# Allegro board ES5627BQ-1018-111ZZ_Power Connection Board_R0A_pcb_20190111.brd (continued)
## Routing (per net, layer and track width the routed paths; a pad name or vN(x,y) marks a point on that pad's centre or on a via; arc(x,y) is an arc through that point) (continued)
VCC12: length 191.4
  TOP w0.381: 49.62,29.94 50.1,30.42 C36.1
  TOP w0.635: CONN5.1 44.59,33.14 ; CONN5.1 43.88,31.49 ; CONN5.1 44.59,31.71 ; CONN5.1 44.82,32.43
  TOP w0.762: CONN20.3 53.95,45.38 ; CONN20.3 51.62,44.39 ; CONN20.3 52.61,46.71 ; CONN20.3 53.61,44.39 ; CONN20.3 51.28,45.38 ; CONN20.3 53.61,46.37 ; CONN20.3 51.62,46.37 ; CONN20.3 52.61,44.05 ; CONN20.16 49.41,49.89 ; CONN20.16 47.42,51.87 ; CONN20.16 49.75,50.88 ; CONN20.16 48.41,49.55 ; CONN20.16 48.41,52.21 ; CONN20.16 47.42,49.89 ; CONN20.16 49.41,51.87 ; CONN20.16 47.08,50.88 ; CONN20.15 52.61,52.21 ; CONN20.15 53.61,51.87 ; CONN20.15 51.62,49.89 ; CONN20.15 51.28,50.88 ; CONN20.15 53.95,50.88 ; CONN20.15 51.62,51.87 ; CONN20.15 52.61,49.55 ; CONN20.15 53.61,49.89 ; CONN20.4 49.75,45.38 ; CONN20.4 49.41,44.39 ; CONN20.4 47.42,44.39 ; CONN20.4 47.42,46.37 ; CONN20.4 48.41,44.05 ; CONN20.4 47.08,45.38 ; CONN20.4 48.41,46.71 ; CONN20.4 49.41,46.37
  V5 w0.635: CONN5.1 44.59,31.71 ; CONN5.1 44.59,33.14 ; CONN5.1 44.82,32.43 ; CONN5.1 43.88,31.49
  V5 w0.762: 51.28,50.88 CONN20.15 ; CONN20.15 53.61,49.89 ; CONN20.15 53.95,50.88 ; CONN20.15 52.61,49.55 ; CONN20.15 52.61,52.21 ; CONN20.15 51.62,51.87 ; CONN20.15 51.62,49.89 ; CONN20.15 53.61,51.87 ; 51.62,46.37 CONN20.3 ; CONN20.3 51.62,44.39 ; CONN20.3 53.61,44.39 ; CONN20.3 52.61,44.05 ; CONN20.3 51.28,45.38 ; CONN20.3 52.61,46.71 ; CONN20.3 53.95,45.38 ; CONN20.3 53.61,46.37 ; CONN20.4 48.41,46.71 ; CONN20.4 49.41,44.39 ; CONN20.4 49.41,46.37 ; CONN20.4 48.41,44.05 ; CONN20.4 49.75,45.38 ; CONN20.4 47.42,46.37 ; CONN20.4 47.42,44.39 ; CONN20.4 47.08,45.38 ; CONN20.16 49.41,49.89 ; CONN20.16 48.41,52.21 ; CONN20.16 47.42,51.87 ; CONN20.16 47.08,50.88 ; CONN20.16 48.41,49.55 ; CONN20.16 47.42,49.89 ; CONN20.16 49.75,50.88 ; CONN20.16 49.41,51.87
  V6 w0.635: 43.88,31.49 CONN5.1 ; CONN5.1 44.82,32.43 ; CONN5.1 44.59,33.14 ; CONN5.1 44.59,31.71
  V6 w0.762: CONN20.16 49.41,49.89 ; CONN20.16 48.41,52.21 ; CONN20.16 47.42,51.87 ; CONN20.16 47.42,49.89 ; CONN20.16 48.41,49.55 ; CONN20.16 49.75,50.88 ; CONN20.16 49.41,51.87 ; CONN20.16 47.08,50.88 ; 48.41,44.05 CONN20.4 ; CONN20.4 47.42,46.37 ; CONN20.4 49.41,46.37 ; CONN20.4 49.41,44.39 ; CONN20.4 47.08,45.38 ; CONN20.4 48.41,46.71 ; CONN20.4 49.75,45.38 ; CONN20.4 47.42,44.39 ; CONN20.15 53.61,51.87 ; CONN20.15 51.28,50.88 ; CONN20.15 52.61,49.55 ; CONN20.15 51.62,49.89 ; CONN20.15 52.61,52.21 ; CONN20.15 53.61,49.89 ; CONN20.15 51.62,51.87 ; CONN20.15 53.95,50.88 ; 51.62,46.37 CONN20.3 ; CONN20.3 52.61,44.05 ; CONN20.3 53.61,44.39 ; CONN20.3 52.61,46.71 ; CONN20.3 51.62,44.39 ; CONN20.3 53.61,46.37 ; CONN20.3 53.95,45.38 ; CONN20.3 51.28,45.38
  BOTTOM w0.381: C127.1 46.62,38.8 ; C118.2 53.46,38.6 53.43,38.63 ; C115.1 46.67,37.79 46.7,37.76 ; C122.2 53.33,39.64 53.25,39.57
  BOTTOM w0.635: CONN5.1 43.88,33.37 ; CONN5.1 44.59,31.71 ; CONN5.1 44.59,33.14 ; CONN5.1 44.82,32.43
  BOTTOM w0.762: CONN20.16 49.75,50.88 ; CONN20.16 47.42,51.87 ; CONN20.16 48.41,52.21 ; CONN20.16 49.41,49.89 ; CONN20.16 48.41,49.55 ; CONN20.16 49.41,51.87 ; CONN20.16 47.42,49.89 ; CONN20.16 47.08,50.88 ; 51.28,50.88 CONN20.15 ; CONN20.15 51.62,51.87 ; CONN20.15 52.61,49.55 ; CONN20.15 52.61,52.21 ; CONN20.15 51.62,49.89 ; CONN20.15 53.61,49.89 ; 47.42,46.37 CONN20.4 ; CONN20.4 48.41,44.05 ; CONN20.4 49.41,44.39 ; CONN20.4 47.08,45.38 ; CONN20.4 49.41,46.37 ; CONN20.4 47.42,44.39 ; CONN20.4 48.41,46.71 ; CONN20.4 49.75,45.38 ; CONN20.3 52.61,46.71 ; CONN20.3 51.62,44.39 ; CONN20.3 52.61,44.05 ; CONN20.3 53.61,44.39 ; CONN20.3 53.61,46.37 ; CONN20.3 51.62,46.37 ; CONN20.3 51.28,45.38
  vias: v1(48.98,37.79) v1(50.66,35.4) v1(51.19,33.34) v1(51.9,38.75) v1(52.39,36.7) v2(45.55,32.76) v2(45.58,31.79) v2(45.6,30.85) v2(46.16,35.2) v2(46.77,32.73) v2(46.8,31.77) v2(46.82,30.83) v2(47.25,35.22) v2(47.76,39.31) v2(47.76,32.73) v2(47.79,31.77) v2(47.81,30.83) v2(48.02,40.58) v2(48.32,35.22) v2(48.55,41.9) v2(48.75,32.76) v2(48.78,31.79) v2(48.8,30.85) v2(49.26,40.51) v2(49.34,39.16) v2(49.39,35.25) v2(49.67,41.93) v2(50.61,41.93) v2(51.01,40.48) v2(51.72,41.83) v2(52.54,41.75)
BS_USB_VCC5P0: length 3.3
  TOP w0.381: v2(81.06,37.18) 81.06,37.23 81,37.29 U2.1
  BOTTOM w0.127: C24.1 82.2,38.42 v1(82.28,38.35)
  BOTTOM w0.381: C24.1 80.99,37.3 81.06,37.23 v2(81.06,37.18)
BS_VSTB_3V3: length 3.6
  TOP w0.381: U1.12 v2(88.81,34.36)
  BOTTOM w0.127: v2(88.81,34.36) 89.29,34.84 v1(89.77,34.84)
  BOTTOM w0.381: C29.1 87.59,34.36 v2(88.81,34.36)
CPLD_VDD1P8: length 37.5
  TOP w0.381: 12.91,39.24 12.89,39.26 C83.1 13.35,39.8 14.1,40.55 R64.1 ; 11.87,39.26 11.88,39.27 C85.1 ; C86.1 10.88,39.21
  TOP w0.635: 6.18,38.48 CONN11.1 ; CONN11.1 7.84,37.76 ; CONN11.1 7.61,38.48 ; CONN11.1 6.9,36.82 ; CONN11.1 7.61,37.05 ; CONN11.1 6.9,38.7
  TOP w0.762: CONN20.22 23.21,52.21 ; CONN20.22 22.22,51.87 ; CONN20.22 21.88,50.88 ; CONN20.22 24.21,51.87 ; CONN20.22 24.55,50.88 ; CONN20.22 24.21,49.89 ; CONN20.22 22.22,49.89 ; CONN20.22 23.21,49.55
  BOTTOM w0.381: C105.1 16.24,40.22 16.24,40.23
  BOTTOM w0.635: CONN11.1 7.84,37.76 ; CONN11.1 7.61,37.05 ; CONN11.1 6.9,38.7 ; CONN11.1 7.61,38.48 ; CONN11.1 6.9,36.82
  BOTTOM w0.762: CONN20.22 24.21,49.89 ; CONN20.22 21.88,50.88 ; CONN20.22 23.21,52.21 ; CONN20.22 24.55,50.88 ; CONN20.22 22.22,49.89 ; CONN20.22 23.21,49.55 ; CONN20.22 22.22,51.87 ; CONN20.22 24.21,51.87
  vias: v1(9.02,39.65) v1(9.42,42.16) v1(11.58,43.36) v1(13.09,39.67) v1(15.33,39.59) v2(9.15,36.92) v2(9.41,37.76) v2(9.64,38.63) v2(9.99,36.92) v2(10.3,37.76) v2(10.42,38.63) v2(10.86,36.95) v2(11.21,37.69) v2(11.34,38.63)
CPLD_VDD1P8_FB: length 4.8
  TOP w0.127: U4.16 v2(15.21,37.54)
  TOP w0.305: U4.16 14.52,39.61 R64.2
  TOP w0.356: R64.2 R63.2
  BOTTOM w0.127: v1(16.16,37.58) 16.12,37.54 v2(15.21,37.54)
CPLD_VDD1P8_PG: length 103.5
  TOP w0.127: CONN19.4 v2(99.96,34.41)
  TOP w0.254: U4.9 v2(13.87,31.45)
  S3 w0.127: v2(13.87,31.45) 14.2,31.78 19.69,31.78 20.32,31.15 24.89,31.15 26.29,32.54 32.33,32.54 33.12,31.75 34.24,31.75 36.36,33.87 36.36,33.88 36.63,34.15 36.64,34.15 38.36,35.87 45.22,35.87 45.5,36.15 84.3,36.15 84.61,36.45 92.81,36.45 94.65,34.61 99.76,34.61 v2(99.96,34.41)
  BOTTOM w0.127: v2(13.87,31.45) v1(12.06,31.45) 11.26,31.45 10.63,32.08 6.79,32.08 CONN13.1
  BOTTOM w0.254: v2(13.87,31.45) 13.87,30.23 R67.2
CPLD_VDD1P8_SS: length 3.4
  TOP w0.254: C87.1 17.52,36.34 v2(17.23,36.34) U4.15
  BOTTOM w0.127: v1(18.15,36.21) 18.01,36.34 v2(17.23,36.34)
CPLD_VDD1P8_VIN: length 2.8
  TOP w0.381: C93.1 9.79,30.8 ; C90.1 10.81,30.8 ; C92.1 11.82,30.78
  BOTTOM w0.127: v2(8.6,31.06) v1(9.53,31.06)
EN_CPLD_VDD1P8_R: length 6.7
  TOP w0.254: U4.11 16.47,33.74 v2(17.02,33.2) 17.51,32.71 C89.1 RB22.2 R66.2 R65.1
  BOTTOM w0.127: v1(17.82,32.86) 17.47,33.2 v2(17.02,33.2)
EN_MANG_1P2_R: length 6.4
  TOP w0.254: RB24.1 30.04,34.61 C94.1 R68.2 ; U5.11 v2(28.84,33.57) 30.02,33.57 R68.2 ; R68.2 30.09,32.5 RB23.2
  BOTTOM w0.127: v2(28.84,33.57) 28.99,33.41 v1(28.99,32.71)
EN_USB_VCC5P0_R: length 7.3
  TOP w0.127: R15.1 v2(69.63,39.21)
  TOP w0.254: R15.1 R14.1 71.38,39.18 CB4.2 RB3.2 73.52,39.11 U2.7
  BOTTOM w0.127: v1(69,39.97) 69,39.84 v2(69.63,39.21)
FB_USB_VCC5P0: length 5.9
  TOP w0.254: U2.5 v2(74.46,41.65) 73.49,41.65 C43.2 73.37,41.57 R16.1 72.04,41.57 R13.2
  BOTTOM w0.127: v1(73.57,41.5) 73.72,41.65 v2(74.46,41.65)
FB_VSTB_3V3: length 6
  TOP w0.254: U1.2 v2(80.75,35.01) 79.4,35.01 C9.2 R2.1
  BOTTOM w0.127: v1(82.08,35.86) 81.8,35.58 R1.1
  BOTTOM w0.254: R1.1 81.58,35.01 v2(80.75,35.01)
FPGA_1V2: length 52.5
  TOP w0.254: R62.2 12.58,27.73 12.71,27.6 v2(14.67,27.6)
  TOP w0.635: 28.28,21.28 CONN10.1 ; CONN10.1 29.22,20.34 ; CONN10.1 29.94,20.56 ; CONN10.1 28.51,20.56 ; CONN10.1 30.16,21.28
  V5 w0.635: 28.51,21.99 CONN10.1 ; CONN10.1 28.51,20.56 ; CONN10.1 29.22,22.22 ; CONN10.1 28.28,21.28 ; CONN10.1 29.94,20.56 ; CONN10.1 30.16,21.28 ; CONN10.1 29.22,20.34 ; CONN10.1 29.94,21.99
  V5 w0.762: 26.08,45.38 CONN20.9 ; CONN20.9 26.42,46.37 ; CONN20.9 28.41,46.37 ; CONN20.9 27.41,44.05 ; CONN20.9 28.41,44.39 ; CONN20.9 26.42,44.39 ; CONN20.9 27.41,46.71 ; CONN20.9 28.75,45.38
  BOTTOM w0.254: v2(14.67,27.6) 20.18,27.6 24.14,23.64 24.14,21.48 24.47,21.15 C80.1
  BOTTOM w0.381: C110.2 27.41,40.78 CONN20.9 ; C79.1 26.63,20.21 v2(26.66,20.19) ; C80.1 v2(25.16,20.16)
  BOTTOM w0.635: 28.28,21.28 CONN10.1 ; CONN10.1 29.22,20.34 ; CONN10.1 28.51,20.56 ; CONN10.1 30.16,21.28 ; CONN10.1 29.94,20.56
  vias: v1(25.39,19.12) v2(26.81,19.42) v2(27.65,20.97) v2(27.65,20.08)
FPGA_1V2_BST: length 3.3
  TOP w0.127: U3.12 20.18,24.83 20.25,24.76 v2(20.41,24.76)
  BOTTOM w0.127: v1(21.3,25.16) 20.89,24.76 v2(20.41,24.76) 20.33,24.68 19.72,24.68 CB10.1
FPGA_1V2_EN_R: length 9
  TOP w0.127: v2(11.67,18.76) 11.18,19.25 R57.1 ; R57.1 12.23,20.79 R56.1 ; R57.1 11.18,21.31 11.17,21.32 R58.2 11.17,22.26 11.18,22.27 C63.1 11.64,22.78 12.19,22.23 U3.7
  BOTTOM w0.127: v2(11.67,18.76) 12.13,19.22 v1(12.56,19.22)
FPGA_1V2_FB: length 6.1
  TOP w0.127: U3.2 12.16,25.48 11.99,25.65 C65.2 R61.1 v2(10.4,24.88)
  BOTTOM w0.127: v1(9.74,24.1) 10.4,24.76 v2(10.4,24.88) 11.08,24.88 R60.2
FPGA_1V2_PG: length 10.9
  TOP w0.127: U3.6 12.62,22.88 12.61,22.89 12.11,22.89 11.34,23.67 11.34,23.74 R59.1 11.23,23.85 8.49,23.85 7.92,24.41 7.92,25.34 7.87,25.39 CONN9.1
  BOTTOM w0.127: CONN9.1 7.87,27.29 8.19,27.61 8.19,28.54 v1(8.43,28.78)
FPGA_1V2_SS: length 3.3
  TOP w0.127: U3.4 12.58,24.18 12.51,24.25 v2(12.35,24.25)
  BOTTOM w0.127: v1(14.34,24.35) 14.31,24.37 C64.1 13.32,24.35 12.46,24.35 v2(12.35,24.25)
FPGA_1V2_SW: length 2.9
  BOTTOM w0.127: v1(20.79,22.75) 20.41,23.13 v2(20.41,23.54)
  BOTTOM w0.254: RB25.1 19.54,22.6 CB10.2 20.35,23.59 v2(20.41,23.54)
FPGA_1V2_VIN: length 12.6
  TOP w0.254: R56.2 13.69,20.77 13.75,20.83 15.31,20.83 15.35,20.87 16.42,20.87 v2(16.8,20.49)
  TOP w0.381: 21.02,25.93 21.04,25.95 C74.1
  BOTTOM w0.254: v2(20.38,25.9) 19.03,25.9 v1(18.98,25.85) 18.22,25.09 18.22,21.56 17.16,20.49 v2(16.8,20.49)
FPGA_1V2_VO: length 6.7
  TOP w0.127: v2(14.77,26.13) U3.1 12,26.13 11.61,26.52 11.46,26.52 C65.1 R61.2 R62.1
  BOTTOM w0.127: v2(14.77,26.13) 15.43,26.79 v1(15.5,26.79)
FPGA_1V2_VREG5: length 5.1
  TOP w0.127: U3.3 12.59,24.83 12.43,24.99 v2(12.4,24.99) 12.1,24.68 R59.2
  BOTTOM w0.127: v1(12.08,26.18) 12.08,25.31 v2(12.4,24.99) 13.11,25.7 CB9.2
FPGA_2V5: length 21.5
  TOP w0.381: 32.17,39.16 32.14,39.18 C123.1 ; C119.1 33.18,39.18 33.16,39.16 ; 31.07,39.18 31.1,39.21 C88.1
  TOP w0.762: CONN20.21 28.41,49.89 ; CONN20.21 28.41,51.87 ; CONN20.21 26.42,51.87 ; CONN20.21 28.75,50.88 ; CONN20.21 26.42,49.89 ; CONN20.21 26.08,50.88 ; CONN20.21 27.41,52.21 ; CONN20.21 27.41,49.55
  BOTTOM w0.381: 31.71,35.58 31.81,35.48 R75.2 ; C124.2 31.63,36.49 31.61,36.52
  BOTTOM w0.635: 32.85,32.86 CONN16.1 ; CONN16.1 33.08,32.14 ; CONN16.1 33.79,33.8 ; CONN16.1 34.51,32.14 ; CONN16.1 33.79,31.92 ; CONN16.1 33.08,33.58 ; CONN16.1 34.51,33.58 ; CONN16.1 34.74,32.86
  vias: v1(31.38,33.77) v2(30.9,38.6) v2(30.92,37.71) v2(31.81,38.63) v2(31.76,37.74) v2(32.73,37.79) v2(32.78,38.6)
FPGA_2V5_EN: length 7
  TOP w0.127: R74.1 43.24,35.32 v2(43.74,34.83)
  TOP w0.356: C113.1 39.95,35.45 39.68,35.72 U6.5
  TOP w0.381: R74.1 R72.1 R73.2 C113.1
  BOTTOM w0.127: v1(44.59,35.17) 44.24,34.83 v2(43.74,34.83)
FPGA_2V5_FB: length 4.7
  TOP w0.356: U6.3 v2(33.94,36.37) 33.23,36.37 R76.2
  BOTTOM w0.127: v1(34.51,35.81) v2(33.94,36.37)
  BOTTOM w0.356: R75.1 C124.1 33.23,36.37 v2(33.94,36.37)
FPGA_2V5_IN: length 2.7
  TOP w0.381: L9.2 42.23,37.51 R72.2
  BOTTOM w0.127: v2(39.41,38.02) v1(40.4,38.02)
HEATER_VCC12: length 89.8
  TOP w0.381: C33.1 95.87,37.99 96.09,38.2 96.09,38.63 96.23,38.78 v2(96.23,38.82) ; C33.1 95.46,38.24 v2(95.46,38.75) ; C33.1 94.6,37.99 L2.1 ; 66.15,30.57 66.23,30.5 C66.1 ; v2(27.98,26.38) 27.75,26.38 27.26,26.87 L5.2 27.57,27.4 v2(28.2,27.4) ; C98.2 62.98,45.35 62.98,45.36 ; v2(87.77,42) LB1.1 v2(88.73,40.86)
  TOP w0.635: CONN8.1 59.86,31.46 ; CONN8.1 58.92,32.4 ; CONN8.1 59.63,32.18 ; CONN8.1 57.98,31.46 ; CONN8.1 59.63,30.75 ; CONN8.1 58.2,32.18
  TOP w0.762: 61.01,44.05 CONN20.1 ; CONN20.1 62.35,44.05 ; CONN20.1 59.68,45.38 ; CONN20.1 61.01,46.71 ; CONN20.1 62.35,45.38 ; CONN20.1 59.68,46.71 ; CONN20.1 62.35,46.71 ; CONN20.1 59.68,44.05
  S3 w0.635: CONN8.1 58.92,32.4 ; CONN8.1 58.92,30.52 ; CONN8.1 59.63,32.18 ; CONN8.1 59.63,30.75 ; CONN8.1 59.86,31.46 ; CONN8.1 58.2,30.75 ; CONN8.1 58.2,32.18 ; CONN8.1 57.98,31.46
  V5 w0.635: 57.98,31.46 CONN8.1 ; CONN8.1 59.63,32.18 ; CONN8.1 58.92,32.4 ; CONN8.1 59.63,30.75 ; CONN8.1 59.86,31.46 ; CONN8.1 58.2,32.18
  V5 w0.762: CONN20.1 62.35,45.38 ; CONN20.1 60.02,46.37 ; CONN20.1 61.01,44.05 ; CONN20.1 62.01,46.37 ; CONN20.1 59.68,45.38 ; CONN20.1 61.01,46.71 ; CONN20.1 62.01,44.39 ; CONN20.1 60.02,44.39
  V6 w0.635: CONN8.1 59.63,32.18 ; CONN8.1 58.2,32.18 ; CONN8.1 57.98,31.46 ; CONN8.1 58.2,30.75 ; CONN8.1 58.92,30.52 ; CONN8.1 58.92,32.4 ; CONN8.1 59.86,31.46 ; CONN8.1 59.63,30.75
  V6 w0.762: 60.02,46.37 CONN20.1 ; CONN20.1 59.68,45.38 ; CONN20.1 62.01,46.37 ; CONN20.1 60.02,44.39 ; CONN20.1 61.01,44.05 ; CONN20.1 62.01,44.39 ; CONN20.1 62.35,45.38 ; CONN20.1 61.01,46.71
  BOTTOM w0.635: CONN8.1 59.63,30.75 ; CONN8.1 58.2,32.18 ; CONN8.1 59.63,32.18 ; CONN8.1 59.86,31.46 ; CONN8.1 58.92,32.4 ; CONN8.1 57.98,31.46
  BOTTOM w0.762: 59.68,45.38 CONN20.1 ; CONN20.1 61.01,46.71 ; CONN20.1 62.01,46.37 ; CONN20.1 61.01,44.05 ; CONN20.1 62.35,45.38 ; CONN20.1 62.01,44.39 ; CONN20.1 60.02,46.37 ; CONN20.1 60.02,44.39
  vias: v1(59.55,37.76) v1(60.77,36.09) v1(62.22,33.8) v1(62.67,37.43) v1(64.6,33.75) v2(29.12,26.54) v2(29.2,27.4) v2(58.99,40) v2(58.96,38.93) v2(59.07,35.07) v2(59.85,38.93) v2(60.13,39.95) v2(60.21,35.04) v2(60.72,31.34) v2(60.84,38.93) v2(60.77,32.56) v2(61.12,40) v2(61.35,35.1) v2(62.09,38.93) v2(62.09,32.56) v2(62.06,31.41) v2(62.34,40.02) v2(62.44,35.1) v2(63.28,32.56) v2(63.31,31.41) v2(63.99,35.15) v2(64.45,32.5) v2(64.53,31.36) v2(88.7,42.19) v2(89.53,42.21) v2(89.48,41.38)
HGATE_MB1: length 5.3
  TOP w0.254: v2(44.84,30.17) 44.84,29.2 Q11.4
  BOTTOM w0.254: R81.2 41.74,30.83 v1(42.38,30.19) 42.4,30.17 v2(44.84,30.17)
HGATE_MB2: length 7.5
  TOP w0.254: Q12.4 v2(62.57,29.33)
  BOTTOM w0.254: R86.2 66.92,29.33 v1(66.38,29.33) v2(62.57,29.33)
I2C_SCL_PS1: length 12.8
  BOTTOM w0.127: v1(38.52,20.39) 38.1,19.98 Q8.C2 38.06,18.97 R45.1 38.06,14.09 R91.1 38.08,13.6 35.82,11.34 CONNB1.19
I2C_SCL_PS2: length 15.9
  TOP w0.127: Q5.C1 92.36,18.38 v2(92.36,17.39) 92.36,15.55 91.91,15.09 R35.1 R93.1 91.91,12.71 92.54,12.08 96.48,12.08 98.07,10.49 CONNB2.19
  BOTTOM w0.127: v2(92.36,17.39) v1(92.36,18.29)
I2C_SDA_PS1: length 15.1
  BOTTOM w0.127: v1(40.52,20.21) 40.39,20.08 Q3.C1 40.39,18.14 40.09,17.84 40.09,15.93 40.37,15.65 R46.1 R92.1 40.37,13.63 40.07,13.33 38.8,13.33 37.09,11.62 CONNB1.20
I2C_SDA_PS2: length 18.3
  TOP w0.127: CONNB2.20 98.12,7.47 97.14,8.45 97.14,9.9 95.39,11.65 92.24,11.65 90.61,13.28 R94.1 R36.1 90.57,14.66 v2(90.57,17.29) Q5.C2
  BOTTOM w0.127: v1(91.15,16.58) 90.57,17.16 v2(90.57,17.29)
LGND_USB_VCC5P0: length 2.6
  TOP w0.254: v2(70.37,39.98) 70.37,40.76 R13.1
  BOTTOM w0.254: C42.2 74.38,39.13 R12.2
  vias: v1(71.73,40.98)
LGND_VSTB_3V3: length 7.5
  TOP w0.254: v2(80.63,32.78) 80.78,32.78 81.06,33.06 U1.5
  BOTTOM w0.127: v1(78.56,30.94) R6.2
  BOTTOM w0.508: R1.2 80.7,32.78 v2(80.63,32.78) 80.35,32.5 C5.2 79.31,31.51 R6.2
MANG_1P2: length 36.9
  TOP w0.356: 25.23,38.93 25.26,38.96 C100.1 25.31,39.57 R70.1 ; C102.1 23.23,38.96 23.28,38.91 ; C104.1 24.24,38.96
  TOP w0.635: CONN15.1 20.71,38.7 ; CONN15.1 20,40.35 ; CONN15.1 20,38.47 ; CONN15.1 20.94,39.41 ; CONN15.1 19.28,40.13 ; CONN15.1 20.71,40.13
  TOP w0.762: 22.22,44.39 CONN20.10 ; CONN20.10 24.21,44.39 ; CONN20.10 21.88,45.38 ; CONN20.10 24.55,45.38 ; CONN20.10 22.22,46.37 ; CONN20.10 23.21,46.71 ; CONN20.10 24.21,46.37 ; CONN20.10 23.21,44.05
  BOTTOM w0.356: C106.2 v2(22.13,40.48)
  BOTTOM w0.635: CONN15.1 20.71,38.7 ; CONN15.1 20,38.47 ; CONN15.1 20,40.35 ; CONN15.1 20.71,40.13 ; CONN15.1 20.94,39.41
  BOTTOM w0.762: CONN20.10 24.55,45.38 ; CONN20.10 23.21,46.71 ; CONN20.10 24.21,44.39 ; CONN20.10 22.22,46.37 ; CONN20.10 21.88,45.38 ; CONN20.10 24.21,46.37 ; CONN20.10 23.21,44.05 ; CONN20.10 22.22,44.39
  vias: v1(23.86,41.75) v2(21.17,40.45) v2(21.19,38.04) v2(21.6,37.48) v2(21.65,39.01) v2(22.21,39.62) v2(22.26,38.47) v2(22.59,37.43) v2(23.33,38.04)
MANG_1P2_FB: length 4.4
  TOP w0.305: U5.16 26.63,38.25 v2(26.71,38.32)
  TOP w0.356: R69.2 27.24,39.59 R70.2 27.21,38.83 v2(26.71,38.32)
  BOTTOM w0.127: v2(26.71,38.32) 26.6,38.42 v1(25.87,38.42)
MANG_1P2_PG: length 94.5
  TOP w0.127: v2(103.41,35.18) 103.73,35.18 104.23,35.68 CONN19.5
  TOP w0.254: U5.9 v2(25.98,31.33)
  S3 w0.127: v2(103.41,35.18) 103.79,34.81 103.79,33.99 101.32,31.51 73.47,31.51 70.63,34.36 43.54,34.36 43.17,34.73 40.35,34.73 36.26,30.64 31.93,30.64 31.21,31.35 29.94,31.35 29.91,31.33 v2(25.98,31.33)
  BOTTOM w0.127: CONN14.1 30.46,30.65 29.79,31.33 v1(27.21,31.33) v2(25.98,31.33)
  BOTTOM w0.254: R71.2 25.98,30.23 v2(25.98,31.33)
MANG_1P2_SS: length 2.9
  TOP w0.254: U5.15 v2(28.79,36.17)
  BOTTOM w0.127: v1(28,35.35) 27.9,35.45 C96.1
  BOTTOM w0.254: v2(28.79,36.17) 28.66,36.29 C96.1
MANG_1P2_VIN: length 2
  BOTTOM w0.356: 23.1,30.83 23.02,30.75 C101.1 ; C99.1 24.04,30.73 24.09,30.78
  BOTTOM w0.381: C103.1 20.71,31.69 20.79,31.77
  vias: v1(21.22,32.5) v2(22.18,32.45) v2(22.18,31.67) v2(23.15,32.45) v2(23.15,31.62)
MB1_PWR_EN: length 77.9
  TOP w0.127: CONN19.7 v2(103.85,36.95)
  S3 w0.127: v2(103.85,36.95) 103.32,36.43 103.32,35.97 103.61,35.68 104.07,35.68 104.18,35.58 104.18,33.5 102.7,32.03 v2(102.7,31.95) 101.84,31.08 73.37,31.08 70.51,33.93 41.83,33.93 38.31,30.42 v2(38.31,30.17)
  BOTTOM w0.127: v2(102.7,31.95) 103.29,31.36 v1(103.57,31.36) ; R79.2 37.75,30.73 v2(38.31,30.17)
PS1_12V_PG: length 5.7
  TOP w0.127: CONN19.11 105.56,39.36 v2(103.95,39.36)
  BOTTOM w0.127: v1(103.14,38.75) 103.74,39.36 v2(103.95,39.36) R40.1 105.68,39.36 R21.1 105.7,38.32 R20.2
PS1_12V_PG_R: length 94.3
  S3 w0.127: v2(31.68,17.95) 32.52,18.8 61,18.8 61.98,19.78 77.48,19.78 78.7,21 94.43,21 104.96,31.53 104.96,37.46 v2(103.9,38.52)
  BOTTOM w0.127: R41.1 33.37,15.1 33.35,15.08 R55.2 32.27,15.08 31.68,15.67 v2(31.68,17.95) Q7.C1 31.68,20.07 v1(31.48,20.26) ; R40.2 103.97,38.45 v2(103.9,38.52)
PS1_A0: length 16.2
  BOTTOM w0.127: CONNB1.3 40.9,4.93 41.98,6.01 44.14,6.01 45.64,7.52 45.64,10.78 R47.2 47.08,12.21 R52.2 48.48,12.21 49.15,12.88 49.15,14.25 v1(49.2,14.3)
PS1_A1: length 7.6
  BOTTOM w0.127: v1(28.84,13.75) 28.84,13.85 29.13,14.14 R49.1 R54.1 30.8,8.79 CONNB1.15
PS1_AC_ALERT: length 5.9
  TOP w0.127: CONN19.15 104.28,42.03 v2(103.97,42.33)
  BOTTOM w0.127: v1(103.08,42.61) 103.36,42.33 v2(103.97,42.33) 104.63,42.33 R28.1 105.7,42.54 R29.1 R30.2
PS1_AC_ALERT_R: length 102.1
  S3 w0.127: v2(43.11,16.02) 43.49,15.65 45.69,15.65 45.99,15.95 61.24,15.95 63.54,18.25 78.12,18.25 79.34,19.47 95.06,19.47 106.51,30.92 106.51,41.45 v2(103.85,44.11)
  BOTTOM w0.127: v1(43.06,20.16) 42.42,19.52 Q3.C2 43.11,18.15 v2(43.11,16.02) 43.11,15.26 R27.2 R26.1 43.37,13 43.04,12.67 39.02,12.67 38.36,12 CONNB1.21 ; v2(103.85,44.11) 104.51,44.11 104.84,43.78 R28.2
PS1_KILL: length 8.3
  BOTTOM w0.127: R44.1 35.5,14.2 35.51,14.22 35.84,14.22 v1(36.09,13.97) 36.02,13.89 36.02,13.31 35.27,12.56 35.27,9.72 34.55,9 CONNB1.18
PS1_ON: length 4.3
  TOP w0.127: CONN19.9 104.43,38.22 v2(103.95,37.74)
  BOTTOM w0.127: R22.1 104.22,37.74 v2(103.95,37.74) 103.08,36.87 102.97,36.87 v1(102.95,36.86)
PS1_ON_R: length 97.7
  S3 w0.127: v2(33.71,20.07) 34.6,19.18 60.84,19.18 61.82,20.16 75.61,20.16 76.83,21.38 94.27,21.38 104.56,31.66 104.56,35.87 104.26,36.16 v2(103.79,36.16)
  BOTTOM w0.127: v1(34.35,20.95) 33.71,20.31 v2(33.71,20.07) Q7.C2 34.4,18.27 34.4,9.86 CONNB1.17 ; R43.1 R42.2 105.6,36.34 R22.2 103.98,36.34 v2(103.79,36.16)
PS1_PDB_FAULT: length 3.3
  BOTTOM w0.127: v1(47.31,14.09) 47.03,14.37 47.03,14.83 R34.1 45.83,15.05 R32.1 44.74,15.1 R33.2
PS1_PDB_FAULT_R: length 23.7
  BOTTOM w0.127: CONNB1.1 46.78,4.93 49.99,8.14 49.99,14.5 49.44,15.05 R34.2 47.71,16.68 46.56,17.82 Q4.C2 47.36,18.79 v1(47.81,19.25)
PS1_PRESENT: length 87.3
  TOP w0.127: CONN19.13 104.25,40.76 v2(103.92,41.09)
  S3 w0.127: v2(103.92,41.09) 105.75,39.26 105.75,31.24 94.75,20.24 79.02,20.24 77.8,19.02 62.3,19.02 60.3,17.02 44.39,17.02 44.12,16.76 v2(43.88,16.76)
  BOTTOM w0.127: v1(45.15,20.19) 44.53,19.57 Q4.C1 44.53,17.41 v2(43.88,16.76) ; v2(103.92,41.09) 104.22,41.39 R53.1 105.71,41.39 R31.1 R48.2
PS1_PRESENT_R: length 101.6
  S3 w0.127: CONNB1.2 39.7,6.2 37.49,8.41 37.49,10.54 34.55,13.48 34.55,16.02 35.7,17.16 42.68,17.16 43.93,18.41 61.16,18.41 62.14,19.4 77.64,19.4 78.86,20.62 94.59,20.62 105.37,31.4 105.37,38.85 v2(103.95,40.28)
  BOTTOM w0.127: v1(103.11,40.66) 103.49,40.28 v2(103.95,40.28) 104.15,40.48 R53.2
PS1_PW_OK: length 7.7
  BOTTOM w0.127: R55.1 32.22,14.17 32.07,14.02 v1(31.83,14.02) 32.01,13.84 CONNB1.16
PS2_12V_PG: length 6
  TOP w0.127: RB7.1 98.46,39.49 v2(99.17,39.49) CONN19.12
  BOTTOM w0.127: v1(99.93,39.95) 99.48,39.49 v2(99.17,39.49) 98.46,39.49 RB7.1 RB6.1
PS2_12V_PG_R: length 41.6
  TOP w0.127: v2(95.46,39.74) 96.12,39.74 96.52,39.34 97.3,39.34 RB7.2
  BOTTOM w0.127: v2(95.46,39.74) 94.79,39.07 94.79,34.85 98.77,30.88 v1(98.77,27.5) 98.77,25.04 94.29,20.57 85.3,20.57 QB2.C1 83.42,15.07 RB14.1 RB18.2
PS2_A0: length 17
  BOTTOM w0.127: CONNB2.3 101.88,6.2 101.04,7.04 101.04,7.95 101.5,8.41 101.5,11.1 98.37,14.22 97.7,14.22 97.28,14.65 RB17.2 RB16.2 96.02,14.65 95.66,15.01 95.05,15.01 94.88,15.17 94.88,15.77 95.83,16.71 v1(95.89,16.71)
PS2_A1: length 15
  TOP w0.127: CONNB2.15 91.81,9.92 90.33,9.92 86.9,13.35 RB15.1 86.85,14.07 RB19.1
  BOTTOM w0.127: v1(93.18,13.79) 92.89,13.49 92.89,8.84 CONNB2.15
PS2_AC_ALERT: length 6.3
  TOP w0.127: CONN19.16 99.6,42.03 v2(99.16,42.47) 98.99,42.64 R37.1
  BOTTOM w0.127: R18.2 R19.1 98.57,42.47 v2(99.16,42.47) 99.36,42.47 v1(99.86,41.98)
PS2_AC_ALERT_R: length 58.2
  TOP w0.127: R37.2 96.53,42.64 v2(96.45,42.56)
  BOTTOM w0.127: v2(96.45,42.56) 96.12,42.23 96.12,39.72 96.7,39.14 96.7,38.63 96.06,37.98 v1(96.06,35.4) 96.06,34.13 99.48,30.71 99.48,26.71 99.15,26.38 99.15,24.73 94.61,20.19 89.06,20.19 Q6.C1 87.44,18.57 87.44,15.16 R24.2 87.63,14.69 87.63,13.53 87.77,13.4 ; 87.77,13.4 88.37,14 89.59,14 90.75,15.16 93.24,15.16 93.77,14.63 95.43,14.63 96.06,14 97.36,14 100.61,10.74 CONNB2.21 ; 87.77,13.4 R25.1
PS2_KILL: length 19.9
  TOP w0.127: CONNB2.18 96.8,7.59 96.76,7.64 96.76,9.62 95.16,11.22 90.43,11.22 88.76,12.9 88.76,14.02 RB20.1
  BOTTOM w0.127: v1(95.1,13.87) 96.8,12.17 CONNB2.18
PS2_ON: length 4.6
  TOP w0.127: RB10.1 98.89,37.97 99.58,38.65 v2(99.76,38.65) 99.96,38.65 100.39,38.22 CONN19.10
  BOTTOM w0.127: v2(99.76,38.65) 99.76,38.32 v1(99.35,37.91)
PS2_ON_R: length 47.1
  TOP w0.127: RB10.2 RB8.2 RB9.1 v2(96.76,35.93) ; QB1.C2 94.37,18.81 94.18,19 v2(94.02,19) 93.34,19.68 89.01,19.68 87.77,18.43 87.77,13.35 90.43,10.69 94.7,10.69 95.53,9.86 CONNB2.17
  BOTTOM w0.127: v2(96.76,35.93) 96.76,34.18 99.86,31.08 99.86,25.72 v1(99.83,25.7) 99.83,24.87 94.02,19.06 v2(94.02,19)
PS2_PDB_FAULT: length 4.6
  TOP w0.127: RB12.1 95.13,14.78 94.39,15.52 v2(94.39,15.71) ; RB12.1 RB11.1 ; RB12.1 RB13.2
  BOTTOM w0.127: v1(94,16.47) 94.15,16.47 94.39,16.23 v2(94.39,15.71)
PS2_PDB_FAULT_R: length 21.4
  TOP w0.127: CONNB2.1 105.52,6.03 105.52,8.98 103.77,10.74 100.26,10.74 97.14,13.86 RB11.2 v2(97.14,17.62) 97.14,18.75 QB1.C1
  BOTTOM w0.127: v2(97.14,17.62) 96.29,18.47 96.19,18.47 96.06,18.59 96.06,18.61 v1(96.06,18.61)
PS2_PRESENT: length 37.1
  TOP w0.127: R51.1 98.74,40.76 v2(99.27,40.76) CONN19.14
  BOTTOM w0.127: 100.92,29.35 100.59,29.68 100.59,40.63 100.47,40.76 v2(99.27,40.76) 99.1,40.58 R39.1 R38.2 ; 100.92,29.35 v1(100.9,29.35) ; 100.92,29.35 100.92,25.43 100.9,25.4 100.21,24.72 94.67,19.17 94.67,18.87 94.33,18.53 93.38,18.53 92.48,19.43 90.33,19.43 Q6.C2
PS2_PRESENT_R: length 56.1
  TOP w0.127: v2(95.04,41.01) 95.06,41.01 95.11,41.06 R51.2
  BOTTOM w0.127: v2(95.04,41.01) 95.04,44.28 96.4,45.64 100.44,45.64 100.75,45.64 102.14,44.24 102.14,31.54 103.57,30.12 v1(103.57,29) 103.57,23.61 99.12,19.17 99.12,14.47 102.27,11.32 102.27,8.4 103.15,7.52 CONNB2.2
PS2_PW_OK: length 20.1
  BOTTOM w0.127: CONNB2.16 94.26,10.08 94.69,10.52 94.69,13.17 93.08,14.78 90.91,14.78 90.45,14.33 90.45,13.39 90.79,13.06 90.79,12.63 90.49,12.34 90.07,12.34 90.06,12.35 87.58,12.35 v1(85.91,14.01) RB18.1
PSU1_SCL: length 94.4
  TOP w0.127: CONN19.17 v2(103.87,43.3)
  S3 w0.127: v2(35.85,15.66) 36.76,16.58 43.27,16.58 43.56,16.29 44.19,16.29 44.44,16.54 60.58,16.54 62.68,18.64 77.96,18.64 79.18,19.86 94.9,19.86 106.13,31.08 106.13,41.04 v2(103.87,43.3)
  BOTTOM w0.127: v1(35.06,16.12) 35.39,16.12 v2(35.85,15.66) 36.67,15.66 R45.2
PSU1_SDA: length 94.7
  TOP w0.127: v2(104.18,45.27) 104.18,45.23 104.84,44.57 CONN19.19
  S3 w0.127: v2(104.18,45.27) 106.89,42.56 106.89,31.08 106.89,30.77 94.66,18.53 93.74,18.53 93.18,19.09 79.64,19.09 78.42,17.87 63.85,17.87 60.78,14.81 41.99,14.81 41.74,15.05 38.86,15.05 v2(38.73,15.18)
  BOTTOM w0.127: v1(39.23,16.22) 39.46,15.99 R46.2 v2(38.73,15.18)
PSU2_SCL: length 35
  TOP w0.127: CONN19.18 v2(99.97,43.3) ; v2(93.8,17.91) 93.8,16.42 93.1,15.71 93.1,14.91 92.82,14.63 R35.2
  BOTTOM w0.127: v2(99.97,43.3) 100.82,42.44 100.82,40.94 100.98,40.79 100.98,30.32 101.59,29.71 v1(101.59,27.58) 101.59,25.55 101.18,25.14 101.18,25.12 95.05,18.99 95.05,18.59 94.36,17.91 v2(93.8,17.91)
PSU2_SDA: length 39.8
  TOP w0.127: R36.2 89.72,14.65 89.72,15.71 89.82,15.82 v2(89.86,15.82) ; CONN19.20 v2(99.97,44.57)
  BOTTOM w0.127: v2(89.86,15.82) 91.81,15.82 93.27,17.27 94.36,17.27 95.47,18.38 95.47,18.87 v1(102.47,25.88) 102.47,29.53 101.36,30.65 101.36,43.18 v2(99.97,44.57)
PSU_VCC12: length 507.1
  TOP w0.381: U7.6 40.91,33.68 v2(41.49,34.26) ; 33.08,22.4 33.08,22.39 C131.1 ; 50.89,21.51 50.91,21.48 C134.1 ; U8.6 v2(68.71,24.8)
  TOP w0.635: 4.7,9.46 CONNB1.P2B_4 ; CONNB1.P2B_4 5.42,9.68 ; CONNB1.P2B_4 6.36,8.74 ; CONNB1.P2B_4 5.42,7.8 ; CONNB1.P2B_4 6.14,9.46 ; CONNB1.P2B_4 4.7,8.02 ; CONNB1.P2B_4 6.14,8.02 ; CONNB1.P2B_4 4.48,8.74 ; CONNB1.P1B_1 24.92,9.68 ; CONNB1.P1B_1 23.98,8.74 ; CONNB1.P1B_1 25.86,8.74 ; CONNB1.P1B_1 25.64,9.46 ; CONNB1.P1B_1 24.2,8.02 ; CONNB1.P1B_1 25.64,8.02 ; CONNB1.P1B_1 24.92,7.8 ; CONNB1.P1B_1 24.2,9.46 ; CONNB2.P2B_1 75.89,9.46 ; CONNB2.P2B_1 74.46,8.02 ; CONNB2.P2B_1 75.17,7.8 ; CONNB2.P2B_1 74.23,8.74 ; CONNB2.P2B_1 74.46,9.46 ; CONNB2.P2B_1 76.11,8.74 ; CONNB2.P2B_1 75.89,8.02 ; CONNB2.P2B_1 75.17,9.68 ; 19.2,8.02 CONNB1.P1B_3 ; CONNB1.P1B_3 20.64,8.02 ; CONNB1.P1B_3 20.64,9.46 ; CONNB1.P1B_3 19.92,9.68 ; CONNB1.P1B_3 19.92,7.8 ; CONNB1.P1B_3 19.2,9.46 ; CONNB1.P1B_3 18.98,8.74 ; CONNB1.P1B_3 20.86,8.74 ; 16.48,8.74 CONNB1.P1B_4 ; CONNB1.P1B_4 16.7,8.02 ; CONNB1.P1B_4 18.14,9.46 ; CONNB1.P1B_4 17.42,7.8 ; CONNB1.P1B_4 16.7,9.46 ; CONNB1.P1B_4 18.14,8.02 ; CONNB1.P1B_4 18.36,8.74 ; CONNB1.P1B_4 17.42,9.68 ; CONNB2.P1B_4 80.39,8.02 ; CONNB2.P1B_4 78.73,8.74 ; CONNB2.P1B_4 80.39,9.46 ; CONNB2.P1B_4 80.61,8.74 ; CONNB2.P1B_4 79.67,9.68 ; CONNB2.P1B_4 79.67,7.8 ; CONNB2.P1B_4 78.95,9.46 ; CONNB2.P1B_4 78.95,8.02 ; CONNB2.P1B_3 82.17,9.68 ; CONNB2.P1B_3 81.46,9.46 ; CONNB2.P1B_3 82.17,7.8 ; CONNB2.P1B_3 82.89,9.46 ; CONNB2.P1B_3 83.11,8.74 ; CONNB2.P1B_3 81.46,8.02 ; CONNB2.P1B_3 82.89,8.02 ; CONNB2.P1B_3 81.23,8.74 ; CONNB2.P1B_2 85.61,8.74 ; CONNB2.P1B_2 85.39,9.46 ; CONNB2.P1B_2 83.73,8.74 ; CONNB2.P1B_2 84.67,7.8 ; CONNB2.P1B_2 83.95,8.02 ; CONNB2.P1B_2 83.95,9.46 ; CONNB2.P1B_2 84.67,9.68 ; CONNB2.P1B_2 85.39,8.02 ; 12.2,8.02 CONNB1.P2B_1 ; CONNB1.P2B_1 11.98,8.74 ; CONNB1.P2B_1 12.2,9.46 ; CONNB1.P2B_1 12.92,9.68 ; CONNB1.P2B_1 12.92,7.8 ; CONNB1.P2B_1 13.86,8.74 ; CONNB1.P2B_1 13.64,9.46 ; CONNB1.P2B_1 13.64,8.02 ; 86.45,8.02 CONNB2.P1B_1 ; CONNB2.P1B_1 87.17,9.68 ; CONNB2.P1B_1 86.45,9.46 ; CONNB2.P1B_1 87.17,7.8 ; CONNB2.P1B_1 86.23,8.74 ; CONNB2.P1B_1 88.11,8.74 ; CONNB2.P1B_1 87.89,9.46 ; CONNB2.P1B_1 87.89,8.02 ; CONNB2.P1B_5 77.17,9.68 ; CONNB2.P1B_5 78.11,8.74 ; CONNB2.P1B_5 77.89,8.02 ; CONNB2.P1B_5 77.17,7.8 ; CONNB2.P1B_5 76.46,9.46 ; CONNB2.P1B_5 76.23,8.74 ; CONNB2.P1B_5 77.89,9.46 ; CONNB2.P1B_5 76.46,8.02 ; 73.95,20.41 CONN6.1 ; CONN6.1 73.24,20.64 ; CONN6.1 74.89,21.35 ; CONN6.1 73.01,21.35 ; CONN6.1 74.67,20.64 ; 67.67,7.8 CONNB2.P2B_4 ; CONNB2.P2B_4 68.61,8.74 ; CONNB2.P2B_4 66.73,8.74 ; CONNB2.P2B_4 67.67,9.68 ; CONNB2.P2B_4 68.39,8.02 ; CONNB2.P2B_4 68.39,9.46 ; CONNB2.P2B_4 66.95,8.02 ; CONNB2.P2B_4 66.95,9.46 ; CONNB2.P2B_2 72.67,9.68 ; CONNB2.P2B_2 73.61,8.74 ; CONNB2.P2B_2 73.39,8.02 ; CONNB2.P2B_2 73.39,9.46 ; CONNB2.P2B_2 71.95,9.46 ; CONNB2.P2B_2 71.95,8.02 ; CONNB2.P2B_2 72.67,7.8 ; CONNB2.P2B_2 71.73,8.74 ; CONNB1.P2B_3 8.86,8.74 ; CONNB1.P2B_3 7.92,7.8 ; CONNB1.P2B_3 7.2,8.02 ; CONNB1.P2B_3 8.64,8.02 ; CONNB1.P2B_3 7.92,9.68 ; CONNB1.P2B_3 8.64,9.46 ; CONNB1.P2B_3 7.2,9.46 ; CONNB1.P2B_3 6.98,8.74 ; 1.98,8.74 CONNB1.P2B_5 ; CONNB1.P2B_5 2.2,9.46 ; CONNB1.P2B_5 2.92,7.8 ; CONNB1.P2B_5 2.92,9.68 ; CONNB1.P2B_5 3.64,8.02 ; CONNB1.P2B_5 3.64,9.46 ; CONNB1.P2B_5 2.2,8.02 ; CONNB1.P2B_5 3.86,8.74 ; CONNB2.P2B_5 65.17,9.68 ; CONNB2.P2B_5 65.89,8.02 ; CONNB2.P2B_5 64.23,8.74 ; CONNB2.P2B_5 66.11,8.74 ; CONNB2.P2B_5 65.17,7.8 ; CONNB2.P2B_5 65.89,9.46 ; CONNB2.P2B_5 64.45,9.46 ; CONNB2.P2B_5 64.45,8.02 ; CONNB2.P2B_3 71.11,8.74 ; CONNB2.P2B_3 70.89,8.02 ; CONNB2.P2B_3 70.89,9.46 ; CONNB2.P2B_3 69.45,9.46 ; CONNB2.P2B_3 69.23,8.74 ; CONNB2.P2B_3 70.17,7.8 ; CONNB2.P2B_3 70.17,9.68 ; CONNB2.P2B_3 69.45,8.02 ; CONNB1.P1B_5 15.64,9.46 ; CONNB1.P1B_5 14.92,9.68 ; CONNB1.P1B_5 15.86,8.74 ; CONNB1.P1B_5 14.2,9.46 ; CONNB1.P1B_5 14.92,7.8 ; CONNB1.P1B_5 13.98,8.74 ; CONNB1.P1B_5 14.2,8.02 ; CONNB1.P1B_5 15.64,8.02 ; CONNB1.P2B_2 11.36,8.74 ; CONNB1.P2B_2 9.7,9.46 ; CONNB1.P2B_2 10.42,9.68 ; CONNB1.P2B_2 10.42,7.8 ; CONNB1.P2B_2 11.14,9.46 ; CONNB1.P2B_2 9.48,8.74 ; CONNB1.P2B_2 9.7,8.02 ; CONNB1.P2B_2 11.14,8.02 ; 21.7,8.02 CONNB1.P1B_2 ; CONNB1.P1B_2 22.42,9.68 ; CONNB1.P1B_2 23.14,9.46 ; CONNB1.P1B_2 21.48,8.74 ; CONNB1.P1B_2 23.36,8.74 ; CONNB1.P1B_2 22.42,7.8 ; CONNB1.P1B_2 23.14,8.02 ; CONNB1.P1B_2 21.7,9.46
  S3 w0.635: 83.95,9.46 CONNB2.P1B_2 ; CONNB2.P1B_2 83.73,8.74 ; CONNB2.P1B_2 85.61,8.74 ; CONNB2.P1B_2 84.67,7.8 ; CONNB2.P1B_2 85.39,8.02 ; CONNB2.P1B_2 85.39,9.46 ; CONNB2.P1B_2 83.95,8.02 ; CONNB2.P1B_2 84.67,9.68 ; 21.48,8.74 CONNB1.P1B_2 ; CONNB1.P1B_2 23.14,9.46 ; CONNB1.P1B_2 22.42,7.8 ; CONNB1.P1B_2 23.14,8.02 ; CONNB1.P1B_2 23.36,8.74 ; CONNB1.P1B_2 21.7,8.02 ; CONNB1.P1B_2 21.7,9.46 ; CONNB1.P1B_2 22.42,9.68 ; CONNB1.P2B_4 6.14,8.02 ; CONNB1.P2B_4 4.48,8.74 ; CONNB1.P2B_4 5.42,9.68 ; CONNB1.P2B_4 6.14,9.46 ; CONNB1.P2B_4 4.7,9.46 ; CONNB1.P2B_4 5.42,7.8 ; CONNB1.P2B_4 6.36,8.74 ; CONNB1.P2B_4 4.7,8.02 ; CONNB1.P2B_1 13.64,9.46 ; CONNB1.P2B_1 12.92,9.68 ; CONNB1.P2B_1 11.98,8.74 ; CONNB1.P2B_1 12.2,8.02 ; CONNB1.P2B_1 13.86,8.74 ; CONNB1.P2B_1 12.92,7.8 ; CONNB1.P2B_1 12.2,9.46 ; CONNB1.P2B_1 13.64,8.02 ; 78.95,9.46 CONNB2.P1B_4 ; CONNB2.P1B_4 80.39,9.46 ; CONNB2.P1B_4 79.67,9.68 ; CONNB2.P1B_4 79.67,7.8 ; CONNB2.P1B_4 78.73,8.74 ; CONNB2.P1B_4 80.61,8.74 ; CONNB2.P1B_4 80.39,8.02 ; CONNB2.P1B_4 78.95,8.02 ; CONNB2.P1B_5 77.17,9.68 ; CONNB2.P1B_5 77.89,8.02 ; CONNB2.P1B_5 77.89,9.46 ; CONNB2.P1B_5 76.23,8.74 ; CONNB2.P1B_5 77.17,7.8 ; CONNB2.P1B_5 76.46,8.02 ; CONNB2.P1B_5 76.46,9.46 ; CONNB2.P1B_5 78.11,8.74 ; 66.95,8.02 CONNB2.P2B_4 ; CONNB2.P2B_4 66.73,8.74 ; CONNB2.P2B_4 68.39,8.02 ; CONNB2.P2B_4 68.39,9.46 ; CONNB2.P2B_4 66.95,9.46 ; CONNB2.P2B_4 67.67,9.68 ; CONNB2.P2B_4 68.61,8.74 ; CONNB2.P2B_4 67.67,7.8 ; 9.7,9.46 CONNB1.P2B_2 ; CONNB1.P2B_2 10.42,7.8 ; CONNB1.P2B_2 11.14,9.46 ; CONNB1.P2B_2 9.7,8.02 ; CONNB1.P2B_2 9.48,8.74 ; CONNB1.P2B_2 11.14,8.02 ; CONNB1.P2B_2 10.42,9.68 ; CONNB1.P2B_2 11.36,8.74 ; CONNB2.P2B_3 70.17,9.68 ; CONNB2.P2B_3 69.45,8.02 ; CONNB2.P2B_3 70.89,8.02 ; CONNB2.P2B_3 69.45,9.46 ; CONNB2.P2B_3 70.89,9.46 ; CONNB2.P2B_3 71.11,8.74 ; CONNB2.P2B_3 70.17,7.8 ; CONNB2.P2B_3 69.23,8.74 ; 2.2,8.02 CONNB1.P2B_5 ; CONNB1.P2B_5 3.86,8.74 ; CONNB1.P2B_5 3.64,9.46 ; CONNB1.P2B_5 1.98,8.74 ; CONNB1.P2B_5 3.64,8.02 ; CONNB1.P2B_5 2.92,7.8 ; CONNB1.P2B_5 2.92,9.68 ; CONNB1.P2B_5 2.2,9.46 ; 86.45,8.02 CONNB2.P1B_1 ; CONNB2.P1B_1 87.17,7.8 ; CONNB2.P1B_1 88.11,8.74 ; CONNB2.P1B_1 86.45,9.46 ; CONNB2.P1B_1 86.23,8.74 ; CONNB2.P1B_1 87.89,9.46 ; CONNB2.P1B_1 87.89,8.02 ; CONNB2.P1B_1 87.17,9.68 ; 7.2,8.02 CONNB1.P2B_3 ; CONNB1.P2B_3 7.92,7.8 ; CONNB1.P2B_3 6.98,8.74 ; CONNB1.P2B_3 7.92,9.68 ; CONNB1.P2B_3 8.64,9.46 ; CONNB1.P2B_3 8.86,8.74 ; CONNB1.P2B_3 8.64,8.02 ; CONNB1.P2B_3 7.2,9.46 ; CONNB1.P1B_1 25.64,8.02 ; CONNB1.P1B_1 24.92,9.68 ; CONNB1.P1B_1 23.98,8.74 ; CONNB1.P1B_1 24.92,7.8 ; CONNB1.P1B_1 24.2,8.02 ; CONNB1.P1B_1 24.2,9.46 ; CONNB1.P1B_1 25.64,9.46 ; CONNB1.P1B_1 25.86,8.74 ; CONNB1.P1B_5 15.64,9.46 ; CONNB1.P1B_5 15.64,8.02 ; CONNB1.P1B_5 14.92,7.8 ; CONNB1.P1B_5 15.86,8.74 ; CONNB1.P1B_5 14.2,8.02 ; CONNB1.P1B_5 14.92,9.68 ; CONNB1.P1B_5 13.98,8.74 ; CONNB1.P1B_5 14.2,9.46 ; CONNB2.P2B_1 75.17,9.68 ; CONNB2.P2B_1 74.23,8.74 ; CONNB2.P2B_1 74.46,9.46 ; CONNB2.P2B_1 75.89,9.46 ; CONNB2.P2B_1 75.89,8.02 ; CONNB2.P2B_1 76.11,8.74 ; CONNB2.P2B_1 75.17,7.8 ; CONNB2.P2B_1 74.46,8.02 ; CONNB2.P1B_3 82.89,8.02 ; CONNB2.P1B_3 82.89,9.46 ; CONNB2.P1B_3 82.17,9.68 ; CONNB2.P1B_3 81.23,8.74 ; CONNB2.P1B_3 81.46,8.02 ; CONNB2.P1B_3 83.11,8.74 ; CONNB2.P1B_3 82.17,7.8 ; CONNB2.P1B_3 81.46,9.46 ; CONNB1.P1B_3 19.92,9.68 ; CONNB1.P1B_3 20.64,9.46 ; CONNB1.P1B_3 19.2,8.02 ; CONNB1.P1B_3 18.98,8.74 ; CONNB1.P1B_3 20.86,8.74 ; CONNB1.P1B_3 20.64,8.02 ; CONNB1.P1B_3 19.92,7.8 ; CONNB1.P1B_3 19.2,9.46 ; 72.67,7.8 CONNB2.P2B_2 ; CONNB2.P2B_2 73.39,9.46 ; CONNB2.P2B_2 71.73,8.74 ; CONNB2.P2B_2 71.95,9.46 ; CONNB2.P2B_2 73.61,8.74 ; CONNB2.P2B_2 72.67,9.68 ; CONNB2.P2B_2 73.39,8.02 ; CONNB2.P2B_2 71.95,8.02 ; CONNB1.P1B_4 18.14,9.46 ; CONNB1.P1B_4 17.42,9.68 ; CONNB1.P1B_4 16.7,8.02 ; CONNB1.P1B_4 18.36,8.74 ; CONNB1.P1B_4 17.42,7.8 ; CONNB1.P1B_4 16.7,9.46 ; CONNB1.P1B_4 18.14,8.02 ; CONNB1.P1B_4 16.48,8.74 ; CONNB2.P2B_5 65.89,9.46 ; CONNB2.P2B_5 64.45,9.46 ; CONNB2.P2B_5 65.17,9.68 ; CONNB2.P2B_5 65.17,7.8 ; CONNB2.P2B_5 66.11,8.74 ; CONNB2.P2B_5 65.89,8.02 ; CONNB2.P2B_5 64.45,8.02 ; CONNB2.P2B_5 64.23,8.74
  V5 w0.635: 73.01,21.35 CONN6.1 ; CONN6.1 73.95,20.41 ; CONN6.1 73.95,22.29 ; CONN6.1 74.67,20.64 ; CONN6.1 74.67,22.07 ; CONN6.1 74.89,21.35 ; CONN6.1 73.24,20.64 ; CONN6.1 73.24,22.07
  V6 w0.635: 29.83,23.72 CONN7.1 ; CONN7.1 29.12,23.94 ; CONN7.1 30.77,24.66 ; CONN7.1 29.83,25.6 ; CONN7.1 28.89,24.66 ; CONN7.1 30.55,23.94 ; CONN7.1 30.55,25.37 ; CONN7.1 29.12,25.37 ; 73.24,22.07 CONN6.1 ; CONN6.1 73.95,22.29 ; CONN6.1 74.67,22.07 ; CONN6.1 73.01,21.35 ; CONN6.1 74.67,20.64 ; CONN6.1 73.95,20.41 ; CONN6.1 73.24,20.64 ; CONN6.1 74.89,21.35
  BOTTOM w0.381: R84.2 v2(70.92,27.83) ; v2(21.3,16.83) 20.99,17.14 C62.1 ; C46.1 67.68,16.22 67.7,16.25
  BOTTOM w0.635: 14.2,9.46 CONNB1.P1B_5 ; CONNB1.P1B_5 14.92,9.68 ; CONNB1.P1B_5 15.64,9.46 ; CONNB1.P1B_5 14.2,8.02 ; CONNB1.P1B_5 13.98,8.74 ; CONNB1.P1B_5 14.92,7.8 ; CONNB1.P1B_5 15.86,8.74 ; CONNB1.P1B_5 15.64,8.02 ; CONNB1.P2B_4 6.14,9.46 ; CONNB1.P2B_4 5.42,9.68 ; CONNB1.P2B_4 5.42,7.8 ; CONNB1.P2B_4 4.7,8.02 ; CONNB1.P2B_4 6.36,8.74 ; CONNB1.P2B_4 4.7,9.46 ; CONNB1.P2B_4 4.48,8.74 ; CONNB1.P2B_4 6.14,8.02 ; CONNB2.P1B_5 77.89,9.46 ; CONNB2.P1B_5 76.23,8.74 ; CONNB2.P1B_5 77.17,7.8 ; CONNB2.P1B_5 76.46,8.02 ; CONNB2.P1B_5 78.11,8.74 ; CONNB2.P1B_5 77.17,9.68 ; CONNB2.P1B_5 76.46,9.46 ; CONNB2.P1B_5 77.89,8.02 ; 75.17,7.8 CONNB2.P2B_1 ; CONNB2.P2B_1 75.89,8.02 ; CONNB2.P2B_1 74.46,9.46 ; CONNB2.P2B_1 74.46,8.02 ; CONNB2.P2B_1 75.89,9.46 ; CONNB2.P2B_1 76.11,8.74 ; CONNB2.P2B_1 75.17,9.68 ; CONNB2.P2B_1 74.23,8.74 ; 78.73,8.74 CONNB2.P1B_4 ; CONNB2.P1B_4 79.67,9.68 ; CONNB2.P1B_4 78.95,9.46 ; CONNB2.P1B_4 79.67,7.8 ; CONNB2.P1B_4 80.39,9.46 ; CONNB2.P1B_4 80.39,8.02 ; CONNB2.P1B_4 80.61,8.74 ; CONNB2.P1B_4 78.95,8.02 ; CONNB1.P1B_3 19.92,9.68 ; CONNB1.P1B_3 18.98,8.74 ; CONNB1.P1B_3 20.64,8.02 ; CONNB1.P1B_3 20.86,8.74 ; CONNB1.P1B_3 19.2,8.02 ; CONNB1.P1B_3 19.92,7.8 ; CONNB1.P1B_3 20.64,9.46 ; CONNB1.P1B_3 19.2,9.46 ; 16.7,9.46 CONNB1.P1B_4 ; CONNB1.P1B_4 18.14,9.46 ; CONNB1.P1B_4 16.48,8.74 ; CONNB1.P1B_4 16.7,8.02 ; CONNB1.P1B_4 17.42,9.68 ; CONNB1.P1B_4 17.42,7.8 ; CONNB1.P1B_4 18.14,8.02 ; CONNB1.P1B_4 18.36,8.74 ; CONNB1.P2B_3 8.64,9.46 ; CONNB1.P2B_3 8.86,8.74 ; CONNB1.P2B_3 7.2,8.02 ; CONNB1.P2B_3 6.98,8.74 ; CONNB1.P2B_3 7.92,9.68 ; CONNB1.P2B_3 8.64,8.02 ; CONNB1.P2B_3 7.2,9.46 ; CONNB1.P2B_3 7.92,7.8 ; CONNB2.P2B_4 68.39,8.02 ; CONNB2.P2B_4 66.95,9.46 ; CONNB2.P2B_4 66.73,8.74 ; CONNB2.P2B_4 67.67,9.68 ; CONNB2.P2B_4 66.95,8.02 ; CONNB2.P2B_4 67.67,7.8 ; CONNB2.P2B_4 68.39,9.46 ; CONNB2.P2B_4 68.61,8.74 ; CONNB1.P2B_2 10.42,9.68 ; CONNB1.P2B_2 11.14,8.02 ; CONNB1.P2B_2 11.36,8.74 ; CONNB1.P2B_2 10.42,7.8 ; CONNB1.P2B_2 9.7,8.02 ; CONNB1.P2B_2 11.14,9.46 ; CONNB1.P2B_2 9.48,8.74 ; CONNB1.P2B_2 9.7,9.46 ; CONNB1.P1B_2 22.42,9.68 ; CONNB1.P1B_2 23.36,8.74 ; CONNB1.P1B_2 21.7,8.02 ; CONNB1.P1B_2 23.14,9.46 ; CONNB1.P1B_2 21.48,8.74 ; CONNB1.P1B_2 22.42,7.8 ; CONNB1.P1B_2 21.7,9.46 ; CONNB1.P1B_2 23.14,8.02 ; CONNB2.P1B_3 82.89,8.02 ; CONNB2.P1B_3 82.17,7.8 ; CONNB2.P1B_3 81.46,8.02 ; CONNB2.P1B_3 81.23,8.74 ; CONNB2.P1B_3 82.89,9.46 ; CONNB2.P1B_3 82.17,9.68 ; CONNB2.P1B_3 83.11,8.74 ; CONNB2.P1B_3 81.46,9.46 ; 24.2,8.02 CONNB1.P1B_1 ; CONNB1.P1B_1 24.2,9.46 ; CONNB1.P1B_1 24.92,7.8 ; CONNB1.P1B_1 23.98,8.74 ; CONNB1.P1B_1 25.64,8.02 ; CONNB1.P1B_1 25.64,9.46 ; CONNB1.P1B_1 24.92,9.68 ; CONNB1.P1B_1 25.86,8.74 ; 72.67,7.8 CONNB2.P2B_2 ; CONNB2.P2B_2 71.95,8.02 ; CONNB2.P2B_2 73.61,8.74 ; CONNB2.P2B_2 73.39,8.02 ; CONNB2.P2B_2 73.39,9.46 ; CONNB2.P2B_2 71.73,8.74 ; CONNB2.P2B_2 72.67,9.68 ; CONNB2.P2B_2 71.95,9.46 ; CONNB1.P2B_5 3.86,8.74 ; CONNB1.P2B_5 3.64,9.46 ; CONNB1.P2B_5 2.92,7.8 ; CONNB1.P2B_5 2.2,8.02 ; CONNB1.P2B_5 2.2,9.46 ; CONNB1.P2B_5 3.64,8.02 ; CONNB1.P2B_5 2.92,9.68 ; CONNB2.P1B_2 85.39,9.46 ; CONNB2.P1B_2 84.67,9.68 ; CONNB2.P1B_2 85.61,8.74 ; CONNB2.P1B_2 85.39,8.02 ; CONNB2.P1B_2 83.95,8.02 ; CONNB2.P1B_2 83.73,8.74 ; CONNB2.P1B_2 83.95,9.46 ; CONNB2.P1B_2 84.67,7.8 ; CONNB1.P2B_1 13.64,8.02 ; CONNB1.P2B_1 11.98,8.74 ; CONNB1.P2B_1 12.2,9.46 ; CONNB1.P2B_1 12.92,7.8 ; CONNB1.P2B_1 12.2,8.02 ; CONNB1.P2B_1 13.64,9.46 ; CONNB1.P2B_1 12.92,9.68 ; CONNB1.P2B_1 13.86,8.74 ; CONNB2.P2B_5 65.89,8.02 ; CONNB2.P2B_5 66.11,8.74 ; CONNB2.P2B_5 65.17,9.68 ; CONNB2.P2B_5 65.17,7.8 ; CONNB2.P2B_5 65.89,9.46 ; CONNB2.P2B_5 64.23,8.74 ; CONNB2.P2B_5 64.45,8.02 ; CONNB2.P2B_5 64.45,9.46 ; CONN6.1 74.89,21.35 ; CONN6.1 73.95,20.41 ; CONN6.1 73.01,21.35 ; CONN6.1 74.67,20.64 ; CONN6.1 73.24,20.64 ; 70.17,7.8 CONNB2.P2B_3 ; CONNB2.P2B_3 69.23,8.74 ; CONNB2.P2B_3 70.17,9.68 ; CONNB2.P2B_3 69.45,9.46 ; CONNB2.P2B_3 70.89,9.46 ; CONNB2.P2B_3 70.89,8.02 ; CONNB2.P2B_3 71.11,8.74 ; CONNB2.P2B_3 69.45,8.02 ; CONNB2.P1B_1 87.17,9.68 ; CONNB2.P1B_1 86.45,9.46 ; CONNB2.P1B_1 86.23,8.74 ; CONNB2.P1B_1 87.89,9.46 ; CONNB2.P1B_1 87.17,7.8 ; CONNB2.P1B_1 86.45,8.02 ; CONNB2.P1B_1 88.11,8.74 ; CONNB2.P1B_1 87.89,8.02
  vias: v1(15.78,14.37) v1(16.68,16.13) v1(18.76,15.51) v1(23.94,15.41) v1(25.92,15.38) v1(70.98,15.79) v1(73.54,15.94) v1(75.55,15.84) v1(77.94,15.84) v1(80.05,15.92) v2(17.18,17.02) v2(17.33,14.17) v2(17.28,13.23) v2(17.31,12.39) v2(18.25,17.02) v2(18.35,13.23) v2(18.4,14.17) v2(18.37,12.39) v2(19.26,17.02) v2(19.42,14.14) v2(19.37,13.2) v2(19.39,12.36) v2(20.31,17.02) v2(20.41,13.23) v2(20.43,12.39) v2(20.46,14.17) v2(21.42,14.17) v2(21.37,13.23) v2(21.4,12.39) v2(22.34,17.02) v2(22.44,13.24) v2(22.49,14.18) v2(22.46,12.4) v2(23.4,17.02) v2(23.51,13.25) v2(23.53,12.41) v2(23.56,14.19) v2(24.45,17.02) v2(24.55,13.25) v2(24.6,14.19) v2(24.57,12.41) v2(25.59,17.01) v2(25.74,14.18) v2(25.69,13.24) v2(25.72,12.4) v2(33.03,28.06) v2(33.03,26.1) v2(33.03,25.14) v2(33.01,24.07) v2(33.01,23.08) v2(33.06,28.97) v2(33.06,27.07) v2(33.82,28.97) v2(33.79,28.06) v2(33.82,27.07) v2(33.79,26.1) v2(33.79,25.14) v2(33.77,24.07) v2(33.77,23.08) v2(34.73,25.9) v2(35.75,25.93) v2(50.84,28.08) v2(50.81,27.17) v2(50.84,26.18) v2(50.81,25.21) v2(50.81,24.25) v2(50.79,23.18) v2(50.79,22.19) v2(51.65,27.17) v2(51.65,25.21) v2(51.65,24.25) v2(51.62,23.18) v2(51.62,22.19) v2(51.67,28.08) v2(51.67,26.18) v2(52.33,24) v2(53.25,24.02) v2(70.04,14.55) v2(70.04,13.63) v2(70.06,12.72) v2(70.22,17.21) v2(71.11,14.55) v2(71.11,13.63) v2(71.13,12.72) v2(71.28,17.21) v2(72.12,14.52) v2(72.12,13.61) v2(72.15,12.69) v2(72.3,17.19) v2(73.16,14.55) v2(73.16,13.63) v2(73.19,12.72) v2(73.34,17.21) v2(74.13,14.55) v2(74.13,13.63) v2(74.15,12.72) v2(74.31,17.21) v2(75.19,14.56) v2(75.19,13.65) v2(75.22,12.73) v2(75.37,17.23) v2(76.26,14.57) v2(76.26,13.66) v2(76.29,12.74) v2(76.44,17.24) v2(77.3,14.57) v2(77.3,13.66) v2(77.33,12.74) v2(77.48,17.24) v2(78.45,14.56) v2(78.45,13.65) v2(78.47,12.73) v2(78.62,17.23)
PSU_VCC12BUS: length 75
  S3 w0.762: CONNB1.22 39.63,8.55 39.76,8.67 39.76,10.3 41.82,12.36 60.56,12.36 v2(61.85,13.64) 64.17,15.97 84.64,15.97 85.56,16.88 89.86,16.88 90.24,16.5 96.73,16.5 100.39,12.84 100.39,11.42 101.88,9.93 CONNB2.22
  BOTTOM w0.127: v2(61.85,13.64) 61.52,13.97 v1(61.52,14.61)
SCREW1: length 24.7
  TOP w0.381: C68.1 5.5,46.11 H4.5 4.5,46.12 C49.1 ; H4.4 6.82,47.34 6.82,45.05 6.49,44.72 CB8.1 ; H4.6 2.93,47.17 2.93,45.61 3.49,45.05 C50.1
  BOTTOM w0.127: H4.5 5,43.59 v1(7.25,41.34)
SCREW2: length 24.2
  TOP w0.381: 101.88,18.76 H5.8 ; 101.88,18.76 100.82,18.76 100.21,19.37 C76.1 ; 101.88,18.76 101.23,19.41 C78.1 101.22,22.44 C76.1 ; C76.1 99.36,22.44 C77.1 99.1,21.21 C75.1 99.07,17.78 100.11,16.73 101.26,16.73 H5.7
  BOTTOM w0.127: H5.1 105.22,20.69 v1(105.22,24.53)
SCREW3: length 21.8
  TOP w0.381: 4.02,19.83 4.03,19.83 C3.1 ; C1.1 6.06,19.65 6.08,19.63 ; C10.1 5.04,19.41 H1.1 ; H1.8 3.01,18.73 C11.1
  BOTTOM w0.127: v1(12.9,15.11) 12.35,14.56 7.18,14.56 H1.4
SCREW4: length 24.7
  TOP w0.381: C4.1 55.18,11.78 55.94,11.02 55.94,9.28 H2.2 ; C13.1 52.77,11 H2.1 54.16,10.13 C2.1 ; C12.1 51.75,9.39 H2.8
  BOTTOM w0.127: H2.2 56.55,9.89 v1(56.55,15.28)
SCREW5: length 24.5
  TOP w0.381: C67.1 94.04,46.31 H3.5 93,45.87 C61.1 ; H3.6 91.55,47.05 87.53,47.05 87.26,47.32 C60.1 C47.1 90.83,48.96 H3.7
  BOTTOM w0.127: H3.7 90.57,49.78 v1(85.53,49.78)
SENSE_12V_HEATER: length 3.2
  TOP w0.254: U8.5 67.52,25.75 67.45,25.67
  BOTTOM w0.381: 59.6,27.7 59.57,27.73 C128.1
  vias: v1(62.04,27.55) v1(64.48,27.75) v2(62.49,26.61) v2(62.49,25.6) v2(62.55,24.48) v2(62.57,23.33) v2(63.79,26.61) v2(63.79,25.6) v2(63.84,24.48) v2(63.87,23.33) v2(65.14,26.61) v2(65.14,25.6) v2(65.19,24.48) v2(65.21,23.33) v2(66.33,26.59) v2(66.33,25.57) v2(66.38,24.45) v2(66.41,23.31)
SENSE_12V_PSU: length 4.4
  TOP w0.254: 42.02,30.37 42.12,30.47 42.12,32.1 41.49,32.73 U7.5
  BOTTOM w0.381: C35.1 42.45,28.59
  vias: v1(45.4,28.47) v1(48.02,28.49) v2(43.1,25.83) v2(43.18,27.86) v2(43.23,26.95) v2(43.23,24.54) v2(43.92,25.25) v2(43.89,23.75) v2(44.04,27.61) v2(43.97,26.44) v2(44.84,27.3) v2(44.84,26.28) v2(44.89,25.16) v2(44.92,24.02) v2(46.14,27.3) v2(46.14,26.28) v2(46.19,25.16) v2(46.21,24.02) v2(47.48,27.3) v2(47.48,26.28) v2(47.53,25.16) v2(47.56,24.02) v2(48.68,27.27) v2(48.68,26.26) v2(48.73,25.14) v2(48.75,24)
SS_USB_VCC5P0: length 3.7
  TOP w0.254: v2(74.86,37.21) 74.86,37.58 75.12,37.84 U2.8
  BOTTOM w0.127: v1(74.38,36.47) 74.86,36.95 v2(74.86,37.21)
  BOTTOM w0.254: C42.1 74.81,37.66 74.81,37.3 74.86,37.25 v2(74.86,37.21)
SS_VSTB_3V3: length 4.4
  TOP w0.254: v2(80.58,33.6) 81.74,33.6 U1.4
  BOTTOM w0.127: R3.1 79.36,34.01 78.75,34.61 78.38,34.61 78.32,34.55 v1(78.2,34.55)
  BOTTOM w0.254: R3.1 v2(80.58,33.6)
SS_VSTB_3V3_R: length 2.3
  BOTTOM w0.127: v1(77.28,32.68) 77.46,32.5 C5.1
  BOTTOM w0.254: R3.2 78.45,32.56 C5.1
SW_USB_VCC5P0: length 7.1
  TOP w0.381: 82.43,48.56 82.42,48.57 DB1.C 80.75,52.21 RB2.2
  BOTTOM w0.381: C24.2 81.95,39.95 v2(82.46,40.45)
  vias: v1(81.27,42.49) v1(83.5,43.78) v2(81.09,45.59) v2(81.98,45.59) v2(82.84,45.61) v2(83.25,40.45) v2(83.86,40.89)
SW_USB_VCC5P0_PLL_C: length 2.8
  TOP w0.127: RB2.1 v2(79.77,51.61)
  TOP w0.381: RB2.1 CB3.1
  BOTTOM w0.127: v1(80.33,50.79) 80.33,51.05 v2(79.77,51.61)
SW_VSTB_3V3: length 3.2
  TOP w0.381: 93.84,34.03 93.91,34.1 C26.2
  BOTTOM w0.127: v1(89.82,32.58) 89.22,32.58 v2(88.91,32.89)
  BOTTOM w0.381: C29.2 v2(88.91,32.89)
SW_VSTB_3V3_PLL_C: length 3.1
  TOP w0.127: v2(95.39,33.16) 95.49,33.26 C26.1
  TOP w0.381: R9.1 96.61,34.1 C26.1
  BOTTOM w0.127: v1(94.45,33.22) 95.34,33.22 v2(95.39,33.16)
USB_VCC5P0: length 42.3
  TOP w0.254: C97.1 27.12,29.19 C95.1 26.63,30.71 U5.10
  TOP w0.381: R17.2 69.48,42.78 69.81,43.12 71.47,43.12 71.73,43.38 71.73,43.61 71.78,43.66 ; CONN20.13 61.45,51.32 C107.1 ; v2(20.58,29.18) 20.33,28.93 CB13.1 18.83,28.93 CB14.1 18.59,28.68 D1.A ; 71.59,43.99 71.54,43.93 C16.1 ; v2(26.48,28.64) 27.01,29.18 C97.1
  TOP w0.635: CONN2.1 71.56,52.8 ; CONN2.1 71.34,52.08 ; CONN2.1 69.9,52.08 ; CONN2.1 71.34,53.51 ; CONN2.1 70.62,51.86
  S3 w0.635: 69.68,52.8 CONN2.1 ; CONN2.1 69.9,52.08 ; CONN2.1 71.56,52.8 ; CONN2.1 71.34,53.51 ; CONN2.1 71.34,52.08 ; CONN2.1 70.62,51.86 ; CONN2.1 69.9,53.51
  S3 w0.762: CONN20.13 62.01,49.89 ; CONN20.13 61.01,49.55 ; CONN20.13 61.01,52.21 ; CONN20.13 62.01,51.87 ; CONN20.13 60.02,51.87 ; CONN20.13 59.68,50.88 ; CONN20.13 60.02,49.89 ; CONN20.13 62.35,50.88
  BOTTOM w0.254: v1(73.19,46.22) 72.76,45.79 v2(71.84,45.79) ; v2(71.69,49.93) 72.91,48.71 v1(73.09,48.71)
  vias: v2(71.83,44.88) v2(71.93,50.98) v2(72.36,44.17) v2(72.47,50.27)
USB_VCC5P0_BODE: length 4.2
  TOP w0.127: C43.1 73.97,42.46 v2(74.08,42.56)
  TOP w0.381: R17.1 71.33,42.48 R16.2 72.4,42.46 C43.1
  BOTTOM w0.127: v2(74.08,42.56) 73.95,42.69 v1(73.95,43.45)
USB_VCC5P0_VIN: length 2.3
  TOP w0.381: 83.92,38.91 84.16,38.67 C28.1 ; C27.1 83.14,38.96
  BOTTOM w0.127: v1(85.43,39.41) 84.47,39.41 v2(84.41,39.36)
VEN_CPLD_VDD1P8: length 88.1
  TOP w0.127: CONN19.6 v2(99.97,35.68) ; R65.2 v2(19.8,35.76)
  S3 w0.127: v2(99.97,35.68) 98.33,35.68 98.11,35.46 95.27,35.46 93.57,37.17 82.34,37.17 81.71,36.53 45.34,36.53 45.06,36.25 35.33,36.25 32.17,33.1 22.46,33.1 v2(19.8,35.76)
  BOTTOM w0.127: v1(99.09,34.26) 99.1,34.26 99.1,34.38 99.97,35.25 v2(99.97,35.68)
VEN_FPGA_1V2: length 107.8
  TOP w0.127: R57.2 10.27,18.94 11.21,18 14.72,18 v2(15.1,17.62) ; v2(104,32.66) 104.48,33.14 CONN19.1
  S3 w0.127: v2(15.1,17.62) 15.63,18.15 30.65,18.15 33.03,20.54 33.9,20.54 34.88,19.56 60.68,19.56 61.67,20.54 69.86,20.54 71.79,22.47 72.67,22.47 75.62,25.43 87.83,25.43 89.45,23.81 96.16,23.81 104,31.64 v2(104,32.66)
  BOTTOM w0.127: v2(15.1,17.62) 15.58,17.62 15.8,17.84 v1(15.85,17.84)
VEN_FPGA_2V5: length 61.9
  TOP w0.127: CONN19.8 v2(99.97,36.95) ; v2(43.92,37.16) 43.92,37.04 R74.2
  S3 w0.127: v2(99.97,36.95) 99.5,36.48 95.2,36.48 94.03,37.65 75.28,37.65 74.98,37.95 69.14,37.95 68.99,37.8 63.32,37.8 63.06,38.05 44.94,38.05 44.04,37.16 v2(43.92,37.16)
  BOTTOM w0.127: v1(98.62,36.1) 98.64,36.1 98.71,36.03 99.05,36.03 v2(99.97,36.95)
VEN_MANG_1P2: length 84
  TOP w0.127: RB24.2 31.46,35.6 31.81,35.25 v2(31.81,31.95) ; CONN19.3 103.54,34.41 103.32,34.19 v2(103.32,34.18)
  S3 w0.127: v2(31.81,31.95) 32.44,31.31 36.09,31.31 40.26,35.49 45.38,35.49 45.63,35.74 69.31,35.74 70.12,34.93 70.6,34.93 73.63,31.89 101.03,31.89 v2(103.32,34.18)
  BOTTOM w0.127: v1(104.11,33.63) 103.57,34.18 v2(103.32,34.18)
VEN_USB_VCC5P0: length 36.8
  TOP w0.127: CONN19.2 v2(99.97,33.14) ; R15.2 v2(70.32,35.4)
  S3 w0.127: v2(99.97,33.14) 99.1,32.28 74.18,32.28 71.05,35.4 v2(70.32,35.4)
  BOTTOM w0.127: v1(99.68,32.38) 99.97,32.66 v2(99.97,33.14)
VMONITOR_3V3: length 99.1
  TOP w0.381: v2(93.83,15.24) 93.83,14.97 RB12.2 ; RB23.1 30.13,31.57 30.54,31.16 30.72,31.16 v2(31,30.88) ; 83.09,21.81 83.04,21.86 C18.1 ; R5.2 75.74,33.17 75.74,27.74 76.58,26.9 78.79,26.9 80.52,25.17 ; L9.1 42.88,39.69 C108.2 ; R14.2 v2(71.36,37.46) ; RB15.2 v2(86.9,15.74) ; C108.2 v2(44.74,39.69) ; C108.2 v2(43.98,40.56) ; R94.2 89.7,13.23 90.08,12.84 v2(90.28,12.84) ; R93.2 92.97,13.61 93.36,13.23 v2(93.36,13.02) ; v2(6.94,29.1) L7.1 v2(5.95,30.02) ; R66.1 v2(19.61,34.74) ; RB9.2 v2(98.43,35.12)
  TOP w0.635: CONN4.1 79.06,24.46 ; CONN4.1 78.35,22.8 ; CONN4.1 77.41,23.74 ; CONN4.1 78.35,24.68 ; CONN4.1 79.29,23.74 ; CONN4.1 79.06,23.03 ; CONN4.1 77.63,24.46 ; CONN4.1 77.63,23.03
  V4 w0.635: CONN4.1 78.35,24.68 ; CONN4.1 77.41,23.74 ; CONN4.1 77.63,23.03 ; CONN4.1 79.06,23.03 ; CONN4.1 78.35,22.8 ; CONN4.1 79.06,24.46 ; CONN4.1 77.63,24.46 ; CONN4.1 79.29,23.74
  V4 w0.762: CONN20.19 36.81,49.89 ; CONN20.19 34.82,51.87 ; CONN20.19 37.15,50.88 ; CONN20.19 34.82,49.89 ; CONN20.19 35.81,52.21 ; CONN20.19 35.81,49.55 ; CONN20.19 36.81,51.87 ; CONN20.19 34.48,50.88 ; CONN20.7 37.15,45.38 ; CONN20.7 34.48,45.38 ; CONN20.7 34.82,44.39 ; CONN20.7 36.81,44.39 ; CONN20.7 35.81,46.71 ; CONN20.7 36.81,46.37 ; CONN20.7 35.81,44.05 ; CONN20.7 34.82,46.37
  BOTTOM w0.381: R19.2 v2(96.73,43.4) ; L8.1 19.11,30.75 v2(18.93,30.93) ; R92.2 38.9,14.19 v2(38.77,14.32) ; 34.28,41.37 34.3,41.34 C116.2 ; R43.2 v2(107.37,37.25) ; RB16.1 v2(95.39,15.56) ; R67.1 v2(13.85,28.62) ; R39.2 v2(96.78,40.58) ; R49.2 28.73,16.11 28.73,17.63 v2(28.68,17.68) ; v2(36.93,13.23) 37.17,13.48 R91.2 ; R25.2 89.77,13.35 v2(90.28,12.84) ; R21.2 v2(107.38,39.34) ; L4.2 v2(37.78,39.41) ; R71.1 25.51,29.26 v2(25.23,29.53) ; R29.2 v2(107.43,42.41) ; R47.1 46.52,13.63 v2(46.52,14.19) R32.2 ; R26.2 41.18,13.56 v2(40.98,13.35) ; C117.1 35.37,41.32 ; v2(96.76,37.97) 96.86,37.97 97.42,38.52 RB6.2 ; R31.2 v2(107.36,41.37) ; C17.1 36.41,41.24
  BOTTOM w0.635: 77.41,23.74 CONN4.1 ; CONN4.1 78.35,22.8 ; CONN4.1 79.06,24.46 ; CONN4.1 79.06,23.03 ; CONN4.1 77.63,23.03 ; CONN4.1 79.29,23.74 ; CONN4.1 77.63,24.46 ; CONN4.1 78.35,24.68
  BOTTOM w0.762: CONN20.7 36.81,44.39 ; CONN20.7 34.82,44.39 ; CONN20.7 34.82,46.37 ; CONN20.7 35.81,44.05 ; CONN20.7 34.48,45.38
  vias: v1(35.99,42.01) v1(81.93,24.58) v1(82.15,22.22) v2(6.02,28.98) v2(6.5,31.11) v2(18.1,31.11) v2(18.16,30.43) v2(83.63,23.72) v2(83.7,22.65) v2(84.67,23.69) v2(84.85,22.7) v2(85.71,23.61) v2(86.12,22.73) v2(86.7,23.72) v2(87.46,22.7) v2(87.79,23.72) v2(88.55,22.7) v2(88.73,23.74)
